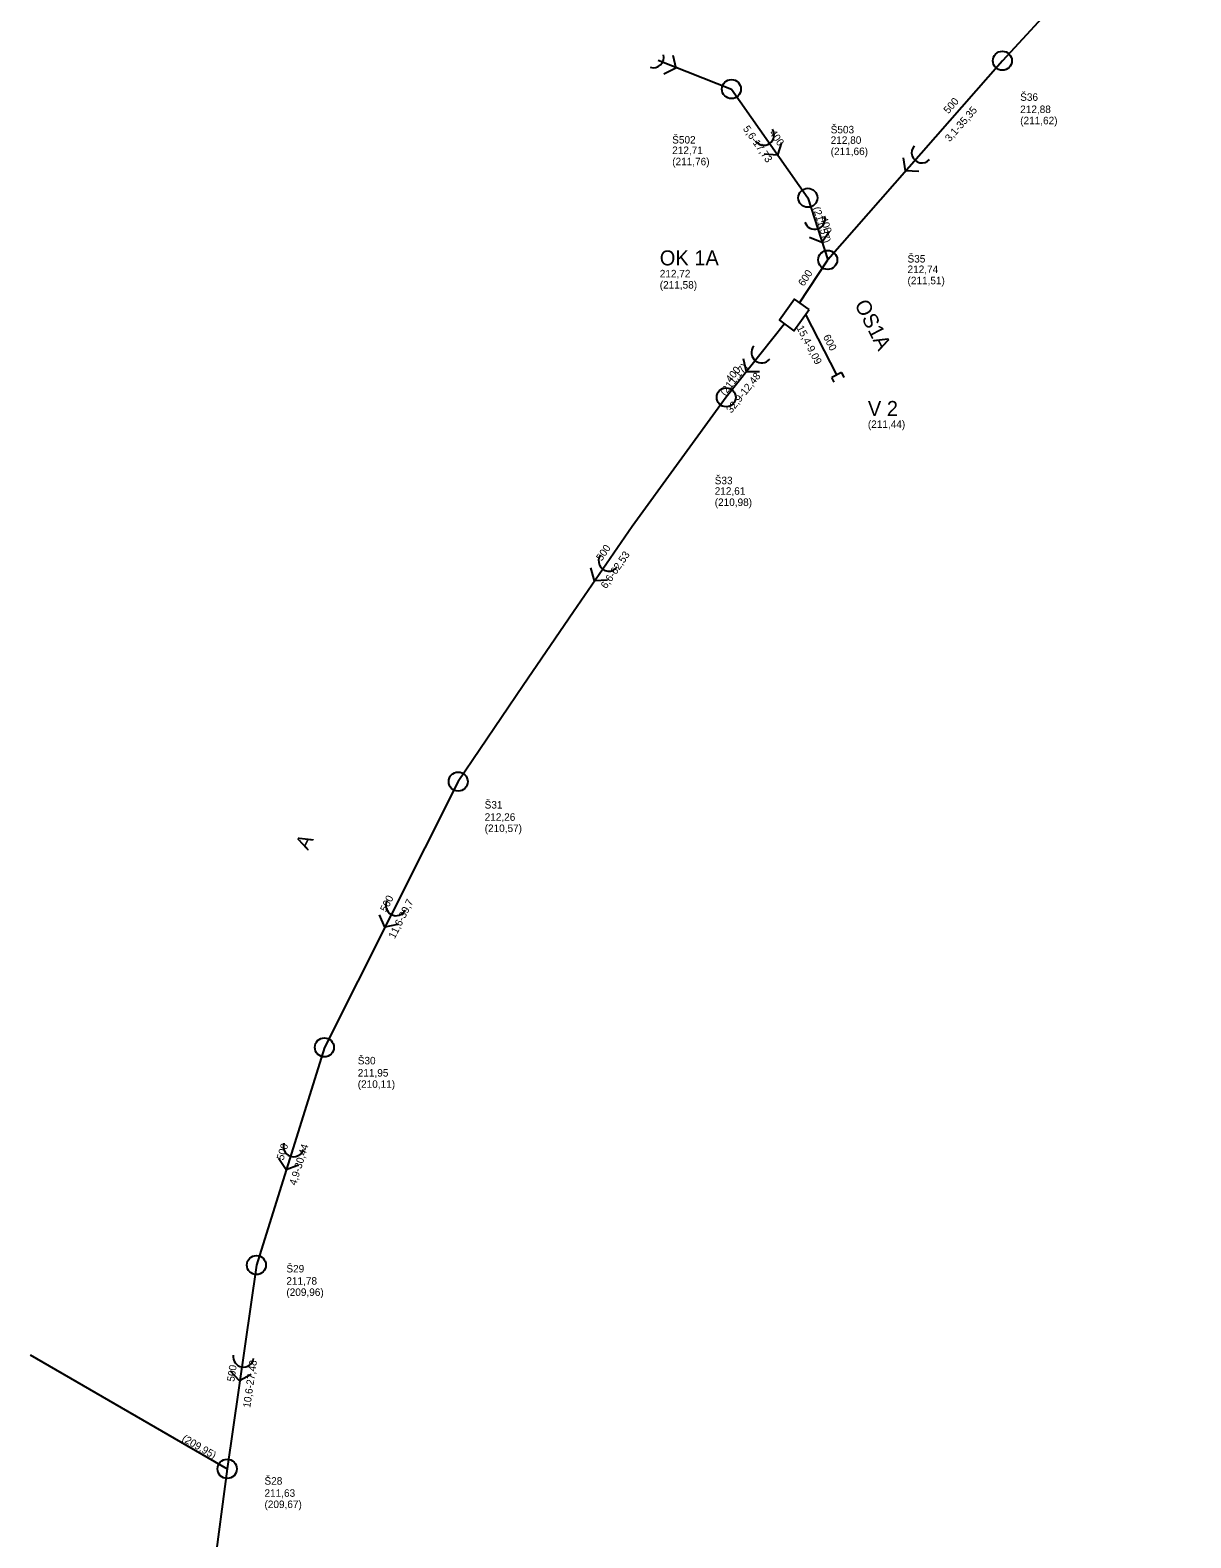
# Model space of a CAD drawing. Extents: x -569540 to -569072, y -1179643 to -1178245.
# Drawn here: x -569441.5 to -569286.7, y -1178944.6 to -1178743.4 of the extents above; entities that cross this region are included whole.
import ezdxf

# ---------------------------------------------------------------- set-up
doc = ezdxf.new("R2010")
doc.units = 0
for name, color, linetype in [('Vrstva 1', 7, 'Continuous'), ('Vrstva 15', 7, 'Continuous'), ('Vrstva 21', 7, 'Continuous'), ('Vrstva 29', 7, 'Continuous'), ('Vrstva 31', 7, 'Continuous'), ('Vrstva 32', 7, 'Continuous'), ('Vrstva 35', 7, 'Continuous'), ('Vrstva 41', 7, 'Continuous'), ('Vrstva 44', 7, 'Continuous'), ('Vrstva 45', 7, 'Continuous'), ('Vrstva 56', 7, 'Continuous'), ('Vrstva 57', 7, 'Continuous')]:
    doc.layers.add(name, color=color, linetype=linetype)

# ---------------------------------------------------------------- blocks, each defined once
blk = doc.blocks.new('100')
at = {"layer": 'Vrstva 1'}
blk.add_circle((0, 0), 1.27, dxfattribs=at)
blk = doc.blocks.new('96')
at = {"layer": 'Vrstva 1'}
for p, q in [((0, 0.72), (0, -0.72)), ((0, 0.72), (0.72, 0.72)), ((0.72, -0.72), (0, -0.72))]:
    blk.add_line(p, q, dxfattribs=at)
blk = doc.blocks.new('86')
at = {"layer": 'Vrstva 1'}
blk.add_lwpolyline([(0.79, 1.37), (1.89, 0), (0.79, -1.38)], dxfattribs=at)
blk.add_arc((-1.37, 0), 1.37, 270, 90, dxfattribs=at)
blk = doc.blocks.new('91')
at = {"layer": 'Vrstva 1'}
blk.add_lwpolyline([(0.79, 1.37), (1.89, 0), (0.79, -1.38)], dxfattribs=at)
blk.add_arc((-1.37, 0), 1.37, 270, 90, dxfattribs=at)

msp = doc.modelspace()

# ---------------------------------------------------------------- linework, layer by layer
at = {"layer": 'Vrstva 15'}
for p, q in [((-569286.71, -1178720.2), (-569311.85, -1178747.44)), ((-569357.77, -1178747.35), (-569347.99, -1178751.22)), ((-569311.85, -1178747.44), (-569335.15, -1178774.02)), ((-569347.99, -1178751.22), (-569337.8, -1178765.73)), ((-569337.8, -1178765.73), (-569335.15, -1178774.02)), ((-569338.9, -1178779.74), (-569335.15, -1178774.02)), ((-569340.92, -1178782.57), (-569348.69, -1178792.36)), ((-569384.44, -1178843.65), (-569402.29, -1178879.11)), ((-569402.29, -1178879.11), (-569411.36, -1178908.16)), ((-569411.36, -1178908.16), (-569415.26, -1178935.36)), ((-569441.54, -1178920.14), (-569415.26, -1178935.36)), ((-569415.26, -1178935.36), (-569419.31, -1178965.81))]:
    msp.add_line(p, q, dxfattribs=at)
msp.add_lwpolyline([(-569348.69, -1178792.36), (-569361.22, -1178809.6), (-569369.08, -1178820.99), (-569375.79, -1178830.84), (-569384.44, -1178843.65)], dxfattribs=at)
at = {"layer": 'Vrstva 21'}
msp.add_line((-569338.12, -1178781.3), (-569333.96, -1178789.38), dxfattribs=at)
at = {"layer": 'Vrstva 31'}
msp.add_lwpolyline([(-569337.64, -1178780.63), (-569339.59, -1178779.26), (-569341.6, -1178782.08), (-569339.68, -1178783.48), (-569337.64, -1178780.63)], dxfattribs=at)
at = {"layer": 'Vrstva 41'}
msp.add_lwpolyline([(-569355.81, -1178746.69), (-569355.41, -1178748.44), (-569357.03, -1178749.22)], dxfattribs=at)
msp.add_arc((-569358.41, -1178746.98), 1.4, 253.1963, 13.2181, dxfattribs=at)

# ---------------------------------------------------------------- block references
at = {"layer": 'Vrstva 29'}
for p, xscale, yscale, rotation in [((-569311.85, -1178747.44), 0.9999999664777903, 0.9999999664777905, -132.99999806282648), ((-569347.99, -1178751.22), 0.9999999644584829, 0.999999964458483, -39.000001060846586), ((-569337.8, -1178765.73), 0.9999999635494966, 0.9999999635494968, -65.00000039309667), ((-569335.15, -1178774.02), 0.9999999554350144, 0.9999999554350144, 53.00000079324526), ((-569348.69, -1178792.36), 0.9999999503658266, 0.9999999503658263, -127.99999981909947), ((-569384.44, -1178843.65), 0.9999999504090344, 0.9999999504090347, -121.00000158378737), ((-569402.29, -1178879.11), 0.9999999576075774, 0.9999999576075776, -113.00000088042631), ((-569411.36, -1178908.16), 0.9999999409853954, 0.9999999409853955, -104.00000032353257), ((-569415.26, -1178935.36), 1.0169561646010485, 1.0169561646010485, -153.0239835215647)]:
    msp.add_blockref('100', p, dxfattribs=dict(at, xscale=xscale, yscale=yscale, rotation=rotation))
at = {"layer": 'Vrstva 31', "xscale": 0.9999999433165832, "yscale": 0.999999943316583, "rotation": -64.0000000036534}
msp.add_blockref('96', (-569333.96, -1178789.38), dxfattribs=at)
at = {"layer": 'Vrstva 41'}
for name, p, xscale, yscale, rotation in [('91', (-569342.9, -1178758.48), 0.9999999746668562, 0.999999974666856, -55.999999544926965), ('86', (-569323.5, -1178760.73), 0.9999999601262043, 0.9999999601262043, -131.99999877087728), ('91', (-569336.47, -1178769.88), 0.9999999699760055, 0.9999999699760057, -73.00000033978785), ('86', (-569344.81, -1178787.47), 0.9999999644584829, 0.999999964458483, -129.00000106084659), ('86', (-569365.15, -1178815.3), 0.9999999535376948, 0.9999999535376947, -126.00000134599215), ('86', (-569393.36, -1178861.38), 0.9999999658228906, 0.9999999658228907, -117.99999982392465), ('86', (-569406.82, -1178893.64), 0.9999999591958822, 0.9999999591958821, -107.99999945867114), ('86', (-569413.31, -1178921.76), 0.9999999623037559, 0.999999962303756, -99.00000013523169)]:
    msp.add_blockref(name, p, dxfattribs=dict(at, xscale=xscale, yscale=yscale, rotation=rotation))

# ---------------------------------------------------------------- texts
at = {"layer": 'Vrstva 32'}
for s, height, p in [('OK 1A', 2, (-569357.55, -1178774.75)), ('212,72 ', 1, (-569357.55, -1178776.35)), ('(211,58)', 1, (-569357.55, -1178777.85)), ('V 2', 2, (-569329.79, -1178794.85)), ('(211,44)', 1, (-569329.79, -1178796.45))]:
    msp.add_text(s, height=height, dxfattribs=at).set_placement(p)
at = {"layer": 'Vrstva 35'}
for s, rotation, p in [('OS1A', 297.24, (-569331.62, -1178779.94)), ('A', 63.28, (-569404.48, -1178852.91))]:
    msp.add_text(s, height=2, rotation=rotation, dxfattribs=at).set_placement(p)
at = {"layer": 'Vrstva 44'}
for s, rotation, p in [('500', 48.77, (-569319.05, -1178754.59)), ('400', 305.08, (-569342.98, -1178757.09)), ('400', 287.74, (-569336.19, -1178768.45)), ('600', 56.71, (-569338.34, -1178777.62)), ('600', 297.24, (-569335.8, -1178784.28)), ('400', 51.57, (-569348.08, -1178790.47)), ('500', 55.4, (-569365.3, -1178814.29)), ('500', 63.28, (-569394.03, -1178861.13)), ('500', 72.67, (-569407.75, -1178894.25)), ('500', 81.84, (-569414.3, -1178923.77))]:
    msp.add_text(s, height=1, rotation=rotation, dxfattribs=at).set_placement(p)
at = {"layer": 'Vrstva 45'}
for s, rotation, p in [('3,1-35,35', 48.77, (-569318.86, -1178758.33)), ('5,6-17,73', 305.08, (-569346.51, -1178756.52)), ('(211,57)', 287.74, (-569337.15, -1178767.1)), ('15,4-9,09', 297.24, (-569339.34, -1178783.07)), ('(211,17)', 51.57, (-569348.84, -1178792.23)), ('32,9-12,48', 51.57, (-569348, -1178794.56)), ('6,6-62,53', 55.4, (-569364.7, -1178817.99)), ('11,6-39,7', 63.28, (-569392.91, -1178864.7)), ('4,9-30,44', 72.67, (-569406.07, -1178897.6)), ('10,6-27,48', 81.84, (-569412.18, -1178927.26)), ('(209,95)', 329.92, (-569421.39, -1178931.58))]:
    msp.add_text(s, height=1, rotation=rotation, dxfattribs=at).set_placement(p)
at = {"layer": 'Vrstva 56'}
for s, p in [('212,88 ', (-569309.47, -1178754.42)), ('(211,62)', (-569309.47, -1178755.92)), ('212,80 ', (-569334.75, -1178758.53)), ('212,71 ', (-569355.89, -1178759.89)), ('(211,66)', (-569334.75, -1178760.03)), ('(211,76)', (-569355.89, -1178761.39)), ('212,74 ', (-569324.5, -1178775.77)), ('(211,51)', (-569324.5, -1178777.27)), ('212,61 ', (-569350.22, -1178805.36)), ('(210,98)', (-569350.22, -1178806.86)), ('212,26 ', (-569380.91, -1178848.87)), ('(210,57)', (-569380.91, -1178850.37)), ('211,95 ', (-569397.84, -1178883.01)), ('(210,11)', (-569397.84, -1178884.51)), ('211,78 ', (-569407.36, -1178910.78)), ('(209,96)', (-569407.36, -1178912.28)), ('211,63 ', (-569410.28, -1178939.09)), ('(209,67)', (-569410.28, -1178940.59))]:
    msp.add_text(s, height=1, dxfattribs=at).set_placement(p)
at = {"layer": 'Vrstva 57'}
for s, p in [('Š36', (-569309.47, -1178752.79)), ('Š503', (-569334.75, -1178757.13)), ('Š502', (-569355.89, -1178758.49)), ('Š35', (-569324.5, -1178774.37)), ('Š33', (-569350.22, -1178803.96)), ('Š31', (-569380.91, -1178847.24)), ('Š30', (-569397.84, -1178881.38)), ('Š29', (-569407.36, -1178909.15)), ('Š28', (-569410.28, -1178937.47))]:
    msp.add_text(s, height=1, dxfattribs=at).set_placement(p)

doc.saveas('drawing.dxf')
